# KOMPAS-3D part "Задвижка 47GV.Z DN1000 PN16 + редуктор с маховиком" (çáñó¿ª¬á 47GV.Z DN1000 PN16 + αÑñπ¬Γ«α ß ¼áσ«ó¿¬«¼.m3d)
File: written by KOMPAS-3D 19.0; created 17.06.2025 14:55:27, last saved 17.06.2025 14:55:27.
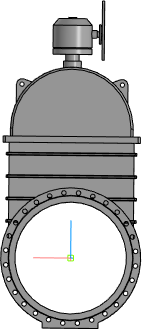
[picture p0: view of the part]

Document properties: Полное имя файла: Задвижка 47GV.Z DN1000 PN16 + редуктор с маховиком.a3d

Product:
- Part/product: Задвижка 47GV.Z DN1000 PN16 + редуктор с маховиком
    Масса: 4591.32
    source file: ..\Рис. 47GV.Z для сервисного отдела.cdw

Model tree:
1. Операция без истории:1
